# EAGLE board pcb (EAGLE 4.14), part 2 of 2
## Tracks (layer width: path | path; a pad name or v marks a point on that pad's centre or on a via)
N$27
  Top 2: 20,-1 -1,-1 -1,20
N$34
  Top 2: 140,-1 161,-1 161,20
N$35
  Top 2: 20,101 -1,101 -1,80
N$36
  Top 2: 161,80 161,101 140,101
N$37
  Bottom 2: 20,-1 -1,-1 -1,20
N$41
  Bottom 2: 140,-1 161,-1 161,20
N$42
  Bottom 2: 20,101 -1,101 -1,80
N$43
  Bottom 2: 161,80 161,101 140,101
N$172
  Top 0.15: 93.5,4 93.5,8.3
N$173
  Top 0.15: 90,7.4 91.1,6.3 91.1,3.6
N$174
  Top 0.15: 85.6,8.1 85.7,8.1 85.7,3.8
N$175
  Top 0.15: 83.4,8.1 83.2,8.1 83.2,4.1
N$176
  Top 0.15: 77.8,8.4 77.9,8.4 77.9,4.3
N$177
  Top 0.15: 75.3,4.3 75.4,4.3 75.4,8.3
N$178
  Top 0.15: 70,4 70,8.3
N$179
  Top 0.15: 67.4,4.2 67.4,7.8 67.9,8.3
N$180
  Top 0.15: 62.2,3.8 62.2,8
N$181
  Top 0.15: 59.4,4.1 59.4,7.8 59.9,8.3
N$182
  Top 0.15: 53.7,4 53.7,6.2 55.4,7.9
N$183
  Top 0.15: 52.9,8 52.9,5.9 51.2,4.2
N$184
  Bottom 0.305: 80.7,4.1 80.6,4
  Bottom 0.61: 49,4.3 49,5.2 49.6,5.8 72.8,5.8 | 72.8,5.8 80.7,5.8 | 80.7,5.8 86.4,5.8 | 86.4,5.8 88.5,5.8 88.5,3.9 | 80.7,5.8 80.7,4.1 | 72.8,5.8 72.8,4 | 91.5,30.9 91.5,27.3 90.2,26 90.2,9.6 86.4,5.8
N$185
  Top 0.15: 52.9,41.8 52.9,24.6 52.7,24.4 52.7,9.2
N$186
  Bottom 0.61: 64.9,4.1 64.9,5.7
N$187
  Bottom 0.61: 56.9,4.1 56.9,5.7
N$188
  Top 0.305: 104.6,0.6 104.7,0.6
  Top 0.406: 105,1.5 105,0.9 104.7,0.6 | 99.1,1.5 100,0.6 104.6,0.6 112.2,0.6 113.3,1.7
N$189
  Top 0.15: 101.6,20.1 101.6,23.3
N$190
  Top 0.15: 97.6,19.9 97.6,21.5 99.2,23.1
N$191
  Top 0.15: 90.8,19.1 93.3,19.1 96.6,22.4 96.6,23.6
N$192
  Top 0.15: 87.9,19.2 87.9,20 91.3,23.4
N$193
  Top 0.15: 94,23.2 94,21.4 93,20.4 89.4,20.4 89.2,20.2 89.2,16.9 90.7,15.4
N$194
  Top 0.813: 96,14.7 105.4,14.7
N$195
  Top 0.15: 104.1,23.4 104.1,20.4 105.7,18.8
N$196
  Top 0.406: 51,87 51.5,87
  Top 0.61: 46.9,91.1 51,87
N$197
  Top 0.61: 51.8,86.8 56.3,86.8
N$198
  Top 0.15: 53.6,86.7 53.7,86.7
  Top 0.406: 51.8,86.7 53.6,86.7 56.3,86.7
N$199
  Top 0.61: 56.5,79.7 56.5,85.2
N$200
  Top 0.15: 56.6,79.6 56.6,85
N$201
  Top 0.15: 52.3,73.9 55.4,73.9 55.5,73.9 55.6,74 56.5,74.9 | 56.4,74.9 56.4,74.8
  Top 0.406: 56.5,74.9 56.5,77.7 | 56.4,74.8 55.6,74
  Top 0.61: 56.4,77.7 56.4,74.9 55.4,73.9
N$202
  Top 0.15: 52.2,73.8 55.5,73.8
N$203
  Top 0.15: 59.8,66 59.8,63.2 56.7,63.2 54.5,61 54.5,57.5
N$204
  Top 0.15: 56.1,71.4 58.5,71.4 59.9,70 59.9,67.4
N$205
  Top 0.15: 53.7,57.5 53.7,60.3 50.8,63.2 45.8,63.2 45.5,63.5 45.5,66
N$206
  Top 0.15: 51.4,71.4 46.9,71.4 45.6,70.1 45.6,67.3
N$207
  Top 0.15: 83.2,77.8 84.4,77.8 84.7,77.5 84.7,75 85,74.7 85.9,74.7 86,74.8
N$208
  Bottom 0.15: 97.2,72.9 98.2,73.9 101.8,73.9 102.9,75 102.9,76.4 100.6,78.7 93.8,78.7 93.8,81.7 93.6,82.1
N$210
  Top 0.406: 89.8,87.5 89.8,91
  Top 0.61: 83.3,83 89,83 | 89,83 90.3,81.7 | 89,83 89.8,83.8 89.8,87.5 95.3,87.5 97.2,89.4 97.2,91.1 99.6,93.5 99.6,95.9
N$211
  Top 0.15: 104,78 104,64.6 105.7,62.9 118.7,62.9 120.7,60.9 120.7,52.5 118.1,49.9 118.1,46.7 118.9,45.9 123.1,45.9 123.6,45.4 125.3,45.4
N$212
  Top 0.61: 75.6,63.4 75.6,61.8
N$214
  Top 0.15: 75.1,80.8 76.3,80.8 79.5,84 79.5,87.5 81.5,89.5 85.3,89.5 86.9,91.1 87.1,91.1
N$215
  Top 0.15: 67.5,69.2 69.3,69.2 70,69.9 70,82 71.1,83.1 73.9,83.1
N$216
  Top 0.15: 73.8,80.5 71,80.5 70.5,80 70.5,67.2 69.8,66.5 68.1,66.5
N$217
  Top 0.61: 74.9,69 74.9,72.3 77.3,74.7 77.3,77.9 | 81.6,83 81,83 80.3,82.3 80.3,77.9 | 80.3,77.9 80.3,76.4 81.3,75.4 | 77.3,77.9 75.8,77.9 | 77.3,77.9 80.3,77.9
N$218
  Top 0.15: 75.9,68.7 75.8,68.7
  Top 0.61: 75.9,68.7 76.9,67.7 76.9,65.3 75.9,64.3
N$219
  Bottom 0.61: 68.4,63.9 73.9,63.9
N$220
  Top 0.8: 37.1,45.7 35.9,45.7
  Top 0.813: 37.1,45.7 37.7,45.1 37.6,43.3 40.7,40.2 40.7,37 42.5,35.2 42.5,18.6 43.3,17.8
N$221
  Top 0.15: 55.3,57.4 55.3,61.1 56.3,62.1 64.7,62.1 66.2,63.6
N$222
  Top 0.15: 52.9,57.3 52.9,60.2 50.5,62.6 45.7,62.6 44.7,63.6 44.7,70.2 46.7,72.2 50.4,72.2 50.4,76.3 51.4,77.3
N$223
  Top 0.15: 52.1,57.6 52.1,60.1 50.2,62 45.5,62 44.2,63.3 44.2,70.5 46.4,72.7 49.9,72.7 49.9,76.3 48.9,77.3
N$224
  Bottom 0.813: 21.2,73.5 26.7,73.5 30.2,77 39.8,77 48.9,86.1
N$225
  Top 0.15: 48.9,57.3 48.9,60.9 48.4,61.4 45.3,61.4 43.7,63 43.7,91.3
N$226
  Top 0.15: 48.1,57.5 48.1,60.9 45.1,60.9 43.2,62.8 43.2,89.2 41.5,90.9
N$227
  Top 0.15: 47.3,57.5 47.3,60.4 44.9,60.4 42.7,62.6 42.7,87.9 39.4,91.2
N$228
  Bottom 0.813: 48.9,86.7 48.9,88.7 49.6,89.4 57.5,89.4 61.5,93.4
N$229
  Top 0.61: 56.2,73.8 61.9,73.8
N$230
  Top 0.61: 62.5,73.1 62.5,68.1 66.4,64.2
N$231
  Top 0.15: 106,71 109.1,71 110.8,72.7
N$232
  Top 0.15: 106,71.7 108.6,71.7 109.5,72.6 109.5,74.1 109.8,74.4 114.5,74.4 115.2,75.1
N$233
  Top 0.15: 99.3,57.8 99.3,60.8 | 99.3,60.8 99.3,62.6 | 99.3,60.8 117.8,60.8 119.1,59.5 119.1,51.5 117.5,49.9 117.5,46.6 119.2,44.9 122.4,44.9 123.6,43.7 135.7,43.7 136.1,44.1
N$234
  Top 0.15: 99.3,55.6 96.5,55.6 95.3,56.8
N$235
  Top 0.15: 98.4,62.6 98.4,59.7 97.6,58.9 93.9,58.9 93,58
N$236
  Top 0.15: 94.9,56 94.9,57 | 94.9,56 94.9,54.5 | 94.9,56 92,56 91.6,56.4 91.6,58.7 92.3,59.4 95.1,59.4 95.3,59.6 95.3,62.5
N$237
  Top 0.15: 98.1,83.7 98.1,84.5 98.4,84.8 101.9,84.8 102.5,85.4 102.5,86.1
N$238
  Top 0.406: 49.2,22.9 49.2,23.1 43.9,17.8
N$239
  Top 0.406: 11.1,56.1 11.4,56.1
  Top 0.813: 11,56.2 11.1,56.1
  Top 1.422: 5.5,56.2 11,56.2 | 11.1,56.1 12.4,54.8
N$240
  Top 1.016: 14.4,54.6 23.9,54.6 24.7,55.4
N$241
  Top 0.406: 24.4,45.7 35.4,45.7
N$242
  Top 0.813: 39.6,53.1 39.6,49.6 35.6,45.6
N$243
  Bottom 0.61: 15.3,23.1 18.3,23.1 18.7,23.5
N$245
  Top 0.15: 59.3,41.5 62.1,41.5 62.6,41 65.8,41 65.8,40.2
N$246
  Top 0.2: 58.5,41.5 58.5,41 58.8,40.7 61.9,40.7 62.5,40.1
N$247
  Top 0.15: 66.3,39.5 68.8,39.5
N$248
  Top 0.15: 69.2,33.5 69.2,36.2
N$249
  Top 0.15: 69.8,33.1 71.1,33.1 72,32.2
N$250
  Top 0.15: 65.8,31.6 69.1,31.6
N$251
  Top 0.15: 65.7,33.8 65.6,33.7
  Top 0.2: 63,39 63,38.3 63.6,37.7 65.7,37.7 65.7,33.8
N$253
  Top 0.15: 57.7,41.7 57.7,40.7 58.3,40.1 61.7,40.1 61.7,38.3 62.2,37.8 62.8,37.8 63.5,37.1 65.1,37.1 65.1,35.1 64.5,35.1 64.1,34.7 64.1,31.8 64.4,31.5 65.1,31.5
N$254
  Top 0.15: 61.2,44.4 62.1,44.4 62.1,42.2 62.9,41.4 66.3,41.4 66.3,40.9 71.1,40.9 72.1,39.9
N$255
  Top 0.15: 74,37.4 74,37.7 75.2,38.9 75.2,40 74.3,40.9 71.8,40.9 71.4,41.3 66.8,41.3 66.8,41.9 63.1,41.9 62.6,42.4 62.6,45.2 61.5,45.2
N$256
  Top 0.2: 73.9,28.9 77.6,28.9
N$257
  Top 0.15: 35.8,41.4 37.5,41.4 38.6,40.3 38.6,39.3
N$258
  Top 0.15: 31.8,37.8 31.8,41.3
N$259
  Top 0.15: 25,38.1 25,39.6 25.7,40.3 27.2,40.3 28.1,41.2
N$260
  Top 0.15: 25.6,27.8 25.5,27.9 25.5,28.8 23.8,30.5 23.8,41.3
N$261
  Top 0.15: 36.9,34.2 36.9,37 36.2,37.7 34.4,37.7 34.3,37.6
N$262
  Bottom 0.61: 15.3,26.3 18.6,26.3 18.7,26.2
N$263
  Top 0.15: 27.2,37.5 29.9,37.5 31.1,36.3 33.1,36.3 33.1,34.3
N$264
  Top 0.15: 33.1,26.7 33.1,26.2 32.5,25.6 29.1,25.6 27.8,26.9
N$265
  Top 0.15: 34.3,31.6 34.3,32.8 | 31.8,28.3 31.8,31.6 | 31.8,31.6 31.8,32.8 | 31.8,31.6 34.3,31.6 | 38.1,31.6 38.1,28.3 38.2,28.2 | 38.1,31.6 38.1,33 | 34.3,31.6 38.1,31.6
N$266
  Top 0.15: 34.3,27.5 35.5,27.5 35.6,27.4
N$267
  Top 0.15: 35.6,26.7 35.6,25.2 37.5,23.3 37.5,17.7 | 37.5,17.7 36.3,17.7 | 37.5,17.7 43.2,17.7
N$269
  Top 0.15: 100.9,78.4 100.9,81.7 99.8,82.8
N$270
  Top 0.15: 101.7,78.3 101.7,82.4 104.3,85 104.3,86.4
N$271
  Top 0.15: 102.4,78.3 102.4,82.3 105.5,85.4 109.7,85.4
N$272
  Top 0.15: 53.5,96.2 61.2,96.2
N$273
  Top 0.15: 61.8,96.2 64,96.2
N$274
  Top 0.2: 66.9,81.6 66.9,84.5
N$275
  Top 0.15: 130.5,66.2 130.5,68.6 130.4,68.7
N$276
  Top 0.15: 120,49.8 123.2,49.8 124.3,50.9
N$277
  Top 0.61: 143.8,36.7 143.8,41.1
N$278
  Top 0.15: 144.2,74.5 148.2,74.5
N$279
  Top 0.15: 144.2,72 148.5,72
N$280
  Top 0.15: 144.2,69.4 148.3,69.4
N$281
  Top 0.15: 144.1,66.9 148.3,66.9
N$282
  Top 0.15: 144.3,64.4 148.3,64.4
N$283
  Top 0.15: 144.3,61.8 148.3,61.8
N$284
  Top 0.61: 151.3,61.8 151.3,74.2
N$285
  Top 0.305: 141.9,61.8 141.9,74.5
N$286
  Top 0.305: 137.5,61.1 140.1,61.1 140.7,61.7 141.9,61.7
N$287
  Top 0.406: 137.6,74.3 138.4,74.3 138.9,73.8 138.9,64.9 137.5,63.5
N$288
  Top 0.305: 123.6,58.7 126.3,58.7 127.7,57.3 133.9,57.3 133.9,62.2 135.1,63.4
N$289
  Top 0.15: 137.7,58.9 138.6,58.9 139.1,58.4 139.1,52.7 139.2,52.6
N$290
  Top 0.15: 14.4,52.1 32.2,52.1 35.6,55.6 45.3,55.6
N$291
  Top 0.15: 45.7,54.8 35.6,54.8 32.3,51.5 16.3,51.5 14.6,49.8
N$292
  Bottom 0.61: 16,40.4 18.7,40.4
N$293
  Bottom 0.61: 16,37.4 18.8,37.4
N$294
  Bottom 0.813: 14.7,42.9 18.9,42.9
N$295
  Bottom 0.61: 20.5,23.8 24.4,23.8 25.6,22.6
N$296
  Top 0.813: 30.1,14.9 30.1,13.2 30.8,12.5 32.2,12.5 33.1,11.6 33.1,7.8 34.2,6.7 34.2,3.7 34.8,3.1 36.1,3.1
N$297
  Bottom 0.8: 20.6,31.8 14.5,31.8 13.3,33 13.3,41.4 14.1,42.2
  Bottom 0.813: 20.8,28.7 20.4,28.6 | 20.8,28.7 20.8,31.8 20.6,31.8 | 20.8,28.7 21.8,28.7 21.8,28
N$298
  Bottom 0.406: 26.8,6.8 26.7,6.9 24.4,6.9 24.4,9.1 24.5,9.2
  Bottom 0.813: 41.2,9.1 41.2,6.3 39.8,4.9 34.8,4.9 31.7,1.9 26.8,6.8 24.4,6.8 24.4,9.4
N$299
  Bottom 0.61: 20.8,26.2 32.3,26.2 36.1,22.4
N$300  (via drill 0.7)  (1 unrouted)
  Bottom 0.406: 10.8,47 16,47 17.4,45.6
  Bottom 0.61: 13,54.5 11.7,54.5 10.8,53.6 10.8,47 10.8,44.2 11.5,43.5
  other vias: 17.4,45.5
N$301
  Bottom 0.61: 11.6,42.5 11.6,30.2 12.5,29.3
N$302
  Bottom 0.813: 21.8,27.9 32.9,27.9 38.5,22.4 38.5,20.8 34.8,17.1 34.8,11.7 35.8,10.7
N$303
  Top 0.305: 9.5,16.2 9.5,21.6 10.6,22.7
N$304
  Top 0.305: 4.9,13.5 6.9,13.5 | 6.9,13.5 9.4,16 | 15.7,10.7 9.7,10.7 6.9,13.5
N$305
  Top 0.305: 15.8,10.3 15.8,8.8 19.2,5.4
N$306
  Top 0.305: 17.3,2.7 18.5,2.7 | 18.5,2.7 18.7,2.7 19.6,3.6 19.6,5 | 18.5,2.7 28.2,2.7 28.3,2.8
N$307
  Top 0.305: 28.4,2.7 28.7,2.7 30.7,4.7
N$308
  Top 0.61: 19.4,10.8 19.4,9.7 24.1,5.1 25.5,5.1
N$309
  Bottom 0.305: 2.7,13.5 2.7,11.9 3.5,11.1 9.3,11.1 12.3,8.1 12.3,2.5 14.2,0.6 21.4,0.6 25.8,5
N$310
  Top 0.15: 32.4,14.9 35.3,14.9 35.8,14.4
N$311
  Top 0.15: 33,17.7 33,17 33.5,16.5 33.5,16 35.1,16 | 35.1,16 35.2,16 | 35.1,16 39.6,16 41.2,14.4
N$312  (via drill 0.7)
  Top 0.406: v1.4,54 1.4,49.9 2,49.3 5.5,49.3
  Bottom 0.406: 5.8,74.2 5.8,61.6 8,59.4 8,55.6 6.3,54 v1.4,54 | 5.8,74.2 5.8,74.3 | 5.8,74.2 5.8,74.7 6.2,75.1 9.6,75.1
N$313
  Top 0.15: 82.1,92.8 82.1,93.9 81.4,94.6 78.9,94.6 78.1,95.4 78.1,98.4 78.8,99.1 95.1,99.1 95.1,98.1
N$314
  Bottom 0.813: 103.1,96 103.1,94.8 103.6,94.3 103.6,89.6 104.9,88.3 118.8,88.3 119.2,87.9 127.1,87.9 128.2,89 128.2,91.7 126,93.9 126,96.2
N$315
  Top 0.61: 156.5,40.7 156.5,48.6
N$316
  Top 0.305: 157.8,29.1 157.8,28.5
  Top 0.61: 157.8,29.1 159.4,30.7 159.4,38.2 156.8,40.8
N$317
  Top 0.61: 150.4,31.4 156.7,31.4
N$318
  Top 0.61: 144.1,41.1 153.8,41.1
N$319
  Top 0.61: 153.9,41.2 153.9,43.5 154,43.6
N$320
  Top 0.61: 155.2,54.3 156.4,55.5
N$321
  Top 0.3: 154.1,83.4 154.1,83.6
  Top 0.61: 151.3,74.5 151.3,76 154.1,78.8 154.1,83.4 | 154.1,83.6 156.8,83.6 158,84.8 158,85.7 155.8,87.9 153.7,87.9
N$322
  Top 0.15: 143.7,86.5 143.7,85.7 144.3,85.1 148.6,85.1 150.1,83.6 151.8,83.6 153.4,85.2 155.2,85.2
N$323
  Bottom 0.15: 156.4,88.2 153.8,88.2 153.6,88
N$324
  Bottom 0.15: 136,74.8 136.1,74.8
  Bottom 0.406: 146.1,86.4 146.1,85.2 147.4,83.9 | 147.4,83.9 148.3,83 | 147.4,83.9 136.1,83.9 136.1,74.8
N$325
  Bottom 0.15: 155.8,81.9 154.6,81.9 153.5,80.8 143.9,80.8 142.8,79.7
N$326
  Bottom 0.15: 137.5,80.7 141.9,80.7 142.7,79.9
N$327
  Bottom 0.15: 131.3,63.9 131.5,63.9 134.9,67.3 139.1,67.3 139.5,67.7 145.7,67.7 147.8,65.6 155,65.6 156.5,67.1
N$328
  Bottom 0.15: 158.2,67.5 159.1,68.4 159.1,74.4 | 159.1,74.4 159.1,87.6 158.8,87.6 158.6,87.8 | 159.1,74.4 158.3,73.6
N$329
  Top 0.813: 147.7,23.7 149.3,22.1 156.7,22.1 156.7,23.1
N$330
  Top 0.61: 156.5,25.8 155.3,25.8 154.6,26.5 154.6,31.3
N$331
  Top 0.305: 158,28.8 157.7,28.8
  Top 0.5: 158,28.8 159.3,27.5 159.3,24.3 158.7,23.7 | 158.7,23.7 158.6,23.6 | 158.7,23.7 158.5,23.5 157.9,23.5 157.7,23.3
N$332
  Top 0.305: 157.1,17.5 157.1,15.2 156.9,15
N$333
  Top 0.305: 124.4,52.8 124.4,56.5 122.5,58.4
N$334
  Top 0.15: 117.2,55.4 117.2,52.4 116.6,51.8 112.6,51.8
N$335
  Top 0.15: 102.8,55.4 102.8,52.2 103.2,51.8 108,51.8
N$336
  Top 0.15: 108.7,49.5 111.7,49.5
N$337
  Top 0.61: 15,88.9 15,96.1
N$338
  Top 0.15: 38.7,13.3 38.7,12.6 46.5,12.6
N$339
  Top 0.15: 44.2,13.3 45.2,13.3 45.9,14 50.3,14 50.3,11 49.8,10.5 48.9,10.5 48.9,9
N$340
  Top 0.813: 43.9,9.9 45.9,9.9 46.8,9
N$341
  Top 0.406: 77.9,2 77.9,1.2
N$342
  Top 0.15: 53.7,41.7 53.7,26.2 54.4,25.5 55.5,25.5 56.3,24.7 56.3,12.1 59.9,8.5
N$343
  Top 0.15: 54.5,41.7 54.5,26.7 55,26.2 55.7,26.2 56.8,25.1 56.8,12.6 59.8,9.6 66,9.6 67,8.6
N$344
  Top 0.15: 55.3,41.7 55.3,26.9 55.9,26.9 57.3,25.5 57.3,12.9 60.2,10 73.7,10 75.3,8.4
N$345
  Top 0.15: 56.1,41.7 56.1,27.6 57.9,25.8 57.9,13.1 60.5,10.5 81.3,10.5 83.1,8.7
N$346
  Top 0.15: 56.9,41.7 56.9,27.5 58.4,26 58.4,13.4 60.9,10.9 88.2,10.9 90.5,8.6
N$347
  Top 0.15: 105.7,69.3 109.3,69.3 111.2,71.2 115.6,71.2 116.5,72.1 116.5,73.2 121.6,73.2 122,73.6
N$348
  Top 0.15: 106,68.5 109.3,68.5 111.5,70.7 115.7,70.7 117.1,72.1 117.1,72.6 124.9,72.6 126.1,71.4 129.4,71.4
N$349
  Top 0.15: 105.9,67.7 118.4,67.7 122.2,63.9
N$350
  Top 0.15: 106,66.9 117.4,66.9 121.8,62.5 128.6,62.5 129.7,61.4
N$351
  Top 0.15: 122.2,68.9 122.2,71.2
N$352
  Top 0.15: 124,66.3 124.8,66.3 127.4,63.7 129.7,63.7
N$354
  Top 0.15: 128.5,84.7 125.4,84.7 | 128.5,84.7 129.1,84.1 129.1,82.3 | 143.5,87.5 131.3,87.5 128.5,84.7
N$355
  Top 0.15: 122.4,84.8 121.4,85.8 117.6,85.8
N$356
  Top 0.305: 135.5,72 134.2,73.3 134.2,75.2 135.1,76.1 150,76.1 150,59.2 150.9,58.3 156.7,58.3
N$357
  Top 0.61: 151.3,61.7 151.3,60.6 151.9,60 158.6,60 159.4,59.2 159.4,56.9 158.5,56
N$358
  Top 0.15: 106,70.1 109.2,70.1 110.7,71.6 115.3,71.6 116,72.3 116,73.6 120.6,73.6 120.9,73.9 120.9,74.6 121.4,75.1 127.1,75.1 127.7,74.5 127.7,72.9 128.2,72.4 132.2,72.4 132.5,72.1 132.5,60.6 131.9,60 122,60 121.2,59.2 121.2,58.1 121.7,57.6 122.4,57.6 123.7,56.3 123.7,53.7 122.9,52.9 122.9,50.8 119.7,50.8 118.7,49.8 118.7,47.1 119.2,46.6 120.6,46.6 121.4,47.4 121.4,49.2 130.6,49.2 131.2,49.8 131.2,51.9 131.5,52.2 137.1,52.2
N$359
  Bottom 0.15: 156.6,69.7 155.1,68.2 139,68.2 138.6,67.8 132.9,67.8 131.8,68.9
N$360
  Bottom 0.15: 156.4,76 155.5,76 155.1,75.6 155.1,71.8 154,70.7 139,70.7 139,69.2 138.2,68.4 134,68.4 132.2,70.2 129.3,70.2 128.5,71 123.6,71
N$361
  Bottom 0.15: 152.2,82.9 152.2,84 153.4,85.2 151.1,87.5 151.1,88 152.5,89.4 155.1,89.4 155.6,89.9 159.2,89.9 159.6,89.5 159.6,61.5 | 159.6,61.5 159.6,42.1 157.3,39.8 155.1,39.8 154.1,38.8 | 159.6,61.5 158.2,61.5
N$363
  Top 0.406: 99.7,95.6 99.7,96.8
  Top 0.61: 104.9,90.4 99.7,95.6
N$364  (via drill 0.5)
  Top 0.15: 90,75.8 89.2,75.8 87.9,74.5 87.9,72.2 v86.2,70.5
  Bottom 0.15: 102,50.3 102,52.9 100.1,54.8 88.4,54.8 88.1,54.5 87,54.5 86.6,54.9 86.6,70.1 v86.2,70.5
N$365
  Bottom 0.15: 78.7,89.7 78.7,89.8
  Bottom 0.2: 78.7,78.9 78.7,84.8
  Bottom 0.813: 78.7,89.8 79.7,90.8 | 78.7,84.8 78.7,89.7
N$366
  Top 0.15: 50.5,57.1 50.5,56.2 47,56.2 45.5,57.7 33.7,57.7 29.6,61.8 12.1,61.8 9.8,59.5 1,59.5 0.4,60.1 0.4,78.9 1.4,79.9
N$367
  Top 0.15: 17.5,96.2 17.5,91.1 16.2,89.8 16.2,85.1 11.3,80.2
N$368
  Top 0.406: 70,1.3 70,2.1
N$369
  Top 0.15: 10.9,62.4 29.8,62.4 34,58.2 45.5,58.2 46,58.7
N$370
  Top 0.15: 3.2,62.4 7.7,62.4 8.7,63.4 11.6,63.4 12.1,62.9 30,62.9 34.2,58.7 43.5,58.7 44.4,59.6
N$371
  Top 0.15: 10.5,67.4 12.1,67.4 13.8,69.1 13.8,82.1 16.9,85.2 16.9,86.4 18.6,88.1 18.6,92.7 19.1,93.2 25,93.2 25.9,94.1 25.9,96
N$372  (via drill 0.5)
  Bottom 0.15: 44.4,59.7 45.3,59.7 45.6,60 47,60 47.5,59.5 47.5,56.6 48.5,55.6 48.5,53.8 v48.3,53.6
N$373  (via drill 0.5)
  Top 0.15: v57.3,60.5 57.4,60.6
  Top 0.2: 56.9,57.3 56.9,60.1 v57.3,60.5
  Bottom 0.15: 67,73.1 67.1,73.2 | 68.2,54.4 68.2,54.3
  Bottom 0.2: v57.3,60.5 61.9,60.5 | 61.9,60.5 63.4,60.5 65.5,62.6 65.5,64.7 66,65.2 69.3,65.2 70.1,66 70.1,69.7 68.9,70.9 67.5,70.9 67,71.4 67,73.1 | 61.9,60.5 61.9,54.9 62.4,54.4 68.2,54.4
N$374
  Top 0.15: 57.7,57 57.7,56.1 51.9,56.1 51.9,55.2 47.9,55.2 47.4,54.6
N$375
  Top 0.15: 58.5,57 58.5,55.6 52.5,55.6 52.5,54.7 49.4,54.7 48.1,53.4
N$376
  Top 0.15: 3.4,77.7 4.4,77.7 4.9,78.2 4.9,85.7 11.1,91.9 11.1,99.7 35.3,99.7 36.7,98.3
N$377
  Top 0.15: 59.3,57.1 59.3,55.1 53.2,55.1 53.2,54.2 50.8,54.2 50,53.4
N$378
  Top 0.15: 3.7,70.1 4.1,70.1 5.4,71.4 5.4,85.5 11.6,91.7 11.6,93.6 13.5,95.7 13.5,99.3 33.9,99.3 34.6,98.4
N$379  (via drill 0.5)
  Top 0.15: 9.3,69.8 8.4,69.8 8.1,69.5 8.1,64.7 8.9,63.9 11.8,63.9 12.4,63.3 30.3,63.3 34.4,59.2 42.1,59.2 v43.3,60.4
  Bottom 0.15: 49.8,53.4 49,54.2 49,55.7 48,56.7 48,59.9 47.4,60.5 43.4,60.5 v43.3,60.4
N$380
  Bottom 0.15: 1.4,62.4 0.7,62.4 0.4,62.7 0.4,84.3 1.5,85.4
N$381
  Bottom 0.15: 8.1,72.6 8.1,63.4 9.1,62.4 | 8.1,72.6 8.1,72.7 | 8.1,72.6 8.1,73.4 8.5,73.8 12,73.8 12.6,74.4 12.6,75.9 12.1,76.4 8.3,76.4 7.8,76.9 7.8,83.4 9.3,84.9
N$382
  Top 0.15: 1.6,74.6 1.6,72.8 1.7,72.7
N$383
  Bottom 0.15: 1.6,72.3 1.5,72.3 0.9,71.7 0.9,64.1 1.3,63.7 3.8,63.7 4.3,63.2 4.3,56.8
N$384
  Top 0.15: 11,82.7 11.9,82.7 12.5,83.3 12.5,94 13.9,95.4 13.9,98.9 26.8,98.9 27.3,98.4 27.3,95.9 28.4,94.8 37,94.8 38.3,96.1 38.3,98.7 38.8,99.2 43.8,99.2 44.6,98.4
N$385
  Top 0.15: 10.9,65 10.9,65.4 14.5,69 14.5,82.1 17.5,85.2 17.5,86.3 19.2,88 19.2,90.9 20.4,92.1 34.9,92.1 38,95.2 41.2,95.2 42,96
N$386
  Top 0.15: 4.5,68.7 4.5,66.1 3.6,65.2
N$387
  Top 0.15: 69.7,14.6 69.7,18.6 72,20.9
N$388
  Top 0.15: 68.4,21.8 67.1,21.8 | 68.4,21.8 69.6,21.8 | 68.4,21.8 68.4,11.7 89.5,11.7 91,10.2 94.5,10.2 96,8.7 96,6 96.4,5.6 125.4,5.6 127.2,3.8
N$389
  Top 0.15: 64.6,14.2 67.2,14.2
N$390
  Top 0.15: 67.1,13.1 67.1,11.3 89.2,11.3 90.8,9.7 94.3,9.7 95.4,8.6 95.4,5.8 96.1,5.1 120,5.1 121.3,3.8
N$391
  Bottom 0.813: 95.9,10.7 93.7,8.8 93.7,4
N$392
  Top 1.016: 5.7,49.3 5.7,50.7
N$393
  Top 0.15: 69.6,13.1 69.6,12.2 81.8,12.2 82.3,12.7 82.3,15.8
N$395
  Bottom 0.15: 91.5,32.7 91.5,36.3
N$396
  Bottom 0.61: 150.2,19.7 151.4,19.7 154.8,16.3 159.1,16.3 159.1,4.5 156,1.4 150.9,1.4 144.4,7.9 119.8,7.9 115.5,12.2
N$397
  Top 0.15: 127.8,45.3 132.7,45.3
N$398
  Bottom 0.15: 104.1,43.3 115,43.3 115.3,43
N$399
  Top 0.15: 122.8,15.2 122.8,17
N$400
  Top 0.15: 124.2,14.4 124.2,13.5 125.4,12.3 125.4,11.4 133,3.8
N$401
  Top 0.15: 116.2,17.7 116.2,19.5
N$402
  Top 0.15: 107.8,14.3 107.7,14.2
  Top 0.813: 122.1,27.4 119.2,27.4 117.3,29.3 113.5,29.3 112,27.8 112,23.9 109.7,21.6 109.7,15 109,14.3 107.8,14.3
N$403
  Top 0.15: 116.5,22.3 120.1,22.3 122.3,20.1
N$404
  Top 0.15: 122.1,19.6 122.1,18.6 121.4,17.9 121.4,7.6 122.9,6.1 126.9,6.1 128.8,4.2 128.8,1.9 | 128.8,1.9 128.8,1.3 128.1,0.6 126.9,0.6 125.6,1.9 | 128.8,1.9 130.7,1.9
N$405
  Top 0.15: 114.7,20 114.7,20.4 113.6,21.5 113.6,23 114,23.4 119.8,23.4 122.1,21.1 124.3,21.1 125.2,20.2 125.2,13.2 125.9,12.5 125.9,11.6 131.1,6.4 136.7,6.4 139.4,3.7
N$406
  Top 0.15: 131.3,1.7 131.3,1.4 131.9,0.8 135.9,0.8 | 135.9,0.8 136,0.8 136.8,1.6 | 135.9,0.8 145.1,0.8 147.4,3.1
N$407
  Top 0.15: 119.1,1.6 119.1,0.9 119.4,0.6 123.7,0.6 124.7,1.6
N$408
  Bottom 0.15: 106.7,23.7 106.7,11.6 111.1,7.3 111.1,2.9 110.6,3.3
N$409
  Bottom 0.15: 109.3,23.4 109.3,22.4 108.7,21.8 107.2,21.8 107.2,12 115.5,3.7
N$410
  Bottom 0.15: 99.3,30.9 101.1,29.1 105.1,29.1 105.7,28.5 105.7,5.6 107.6,3.7
N$411
  Bottom 0.15: 96.6,30.8 97.3,30.8 99.5,28.6 104.8,28.6 105.2,28.2 105.2,5.6 102.6,3
N$412
  Top 0.15: 84.1,16.3 84.1,18.2 87.1,21.1 87.5,21.5 88.6,21.5 90.2,23.1 90.2,26 91.4,27.2 91.4,31
N$413
  Top 0.61: 27.5,14 27.1,14
  Top 0.813: 30.2,15.3 28.8,15.3 27.5,14
N$414
  Bottom 0.406: 38.7,10.8 38.7,19.1 40.1,20.5 40.1,23.3 34.4,29 23.4,29 22.5,29.9 22.5,40.7 22.9,41.1 22.9,48 21.7,49.2
N$415
  Top 0.61: 15.1,33.7 13.7,32.3 13.7,18.9 16.1,16.5 17.3,16.5
N$416
  Top 0.61: 19.4,10.7 19.4,17.6 18.7,18.3 16.2,18.3 15.4,19.1 15.4,22.9 16.3,23.8 18.7,23.8
N$417
  Top 0.406: 31.2,8.9 31.2,7.9 32.8,6.3 32.8,2.5 34.8,0.5 37.6,0.5 38.4,1.3
N$418
  Bottom 0.61: 13.2,16.2 13.2,14 14.5,12.7 19.8,12.7 21.6,10.9
N$419
  Top 0.61: 24.2,16.6 24.3,16.6 23.6,16.6
  Top 0.813: 24.3,16.6 27.4,16.6 | 24.2,16.6 22.6,18.2 22.6,38.7 21,40.3 | 23.6,16.6 21.7,14.7 21.7,10.4 21.6,10.3
N$420
  Top 0.15: 48.3,11.7 48.3,10.9 45.6,10.9 44.6,11.9 39.6,11.9 38.5,10.8
N$421
  Top 0.813: 32,73.1 32,67.3 29.8,65.1 16.8,65.1
N$422
  Top 0.406: 85.7,1.2 85.7,2.3
N$423
  Bottom 0.406: 41.3,3.2 41,3.2
N$424
  Top 0.15: 36.9,26.8 36.9,25.6 38,24.5 40.8,24.5 41.7,25.4 41.7,34.7 39.4,37
N$425
  Top 0.406: 23.9,45.7 17.6,45.7 10.6,38.6 10.6,22.8
N$426  (via drill 0.5)
  Bottom 0.15: v40.9,49.1 39.9,49.1 39.5,48.7 39.5,46.1 29.7,36.3 29.7,36.1
N$427
  Top 0.15: 30.5,34.2 30.5,35.2 29.7,36
N$428
  Top 0.15: 30.5,28.3 30.5,29.2 29.6,30.1 28.5,30.1 28.2,30.4 28.2,34.8
N$429  (via drill 0.5)
  Bottom 0.15: 40.7,47.6 40.7,46.6 30.9,36.8 30.9,35.3 30.5,34.9 v28.2,34.9
N$430
  Top 0.15: 45.5,50.8 43.6,50.8 43.2,50.4 43.2,49.7 41.2,47.7
N$431
  Bottom 0.813: 54.6,22.8 54.6,18.6 46.7,10.5
N$432
  Bottom 0.61: 36.1,22.2 36.1,20.4 33.1,17.4 33.1,15 28.8,10.7
N$433
  Bottom 0.813: 79.5,92.1 76.1,92.1 74.9,93.3 74.9,97.5 74.1,98.3 59.6,98.3 58.9,97.6 58.9,94.5 59.8,93.6 61.6,93.6
N$434
  Top 0.15: 30.6,18.4 28.6,18.4 28,19
N$435
  Bottom 0.15: 28,18.9 30.1,16.8 30.1,14.5 27,11.4 27,8.5 28.5,7 38.4,7 39.9,8.5 39.9,11.3 40.5,11.9 41.4,11.9
  Bottom 0.406: 28,18.9 27.9,18.9
N$436
  Top 0.813: 5.5,50.8 8.1,50.8 12,46.9 24.6,46.9 25.6,47.9
N$437
  Bottom 0.813: 54.3,23.5 46.7,31.3 25.6,31.3 25.6,47.9
N$438
  Top 0.15: 51.3,57 51.3,55.7 47,55.7 45.4,57.3 33.4,57.3 29.4,61.3 12.4,61.3 9.7,58.6 6.8,58.6
N$439
  Top 0.813: 93.6,1.9 93.6,1.2
N$440  (via drill 0.7)
  Top 0.813: v47.1,6.5 47.1,8.2
  Bottom 0.7: 140.4,0.6 141.1,1.3
  Bottom 0.813: v47.1,6.5 46.4,5.8 46.4,1.3 47.1,0.6 140.4,0.6
N$441
  Bottom 0.813: 141.2,1.4 144,4.2 144,5.5
N$442  (via drill 0.7)
  Top 0.305: 144,3.5 v144,5.6
  Top 0.406: 144,7.2 143.9,7.3
  Top 0.813: v144,5.6 144,7.2
N$443
  Top 0.813: 50.2,1.1 49.9,1.1 | 50.2,1.1 93.6,1.1 | 50.2,1.1 47.1,1.1 46.3,1.9 46.3,3.8 48.5,6 51.2,6 51.2,7.8
N$444
  Top 0.305: 53.7,2.3 53.7,2.2
N$445
  Top 0.406: 53.7,1.1 53.7,2
N$446
  Top 0.406: 61.9,1.9 61.9,1.2
N$447
  Top 0.2: 96.6,1.6 96.6,0.3 42.5,0.3 41.3,1.5
N$448
  Bottom 0.8: 39.9,54.8 39.2,55.5 29,55.5
  Bottom 0.813: 39.9,54.8 39.9,53.5
N$449
  Top 0.15: 127.5,16.2 127.5,14.1 129.7,11.9
N$450
  Top 0.305: 98.7,3.3 97.4,4.6 95.7,4.6 95.1,3.9 95.1,1.2 93.7,1.2
N$451
  Top 0.15: 132.6,17.5 131.8,18.3 128.5,18.3 127.5,17.3
N$452
  Top 0.15: 140.2,12.9 140.2,17.2 140.3,17.3
N$453
  Top 0.305: 135.1,12.8 135.1,13.1 137.7,15.7
N$454
  Top 0.15: 140.5,24.1 140.5,22.3 135.5,17.3
N$455
  Top 0.15: 157,20.4 152.9,20.4 152.9,20.9 145.5,20.9 142.7,18.1
N$456
  Top 0.15: 135.4,15.7 135.4,14.6 133.5,12.7 133.5,10.7 134.2,10 135.5,10 136.3,10.8 136.3,13.1 136.9,13.7 138,13.7 138.8,12.9 138.8,8.8 139.8,7.8 142,7.8
N$457
  Top 0.15: 141.9,3.5 141.9,4.8 137.5,9.2 137.5,10.9 136,9.4 129.9,9.5
N$458
  Top 0.15: 142.6,24.2 142.6,20 140.7,18.1
N$459
  Bottom 0.305: 131.7,24 131.7,23.5 137.7,17.5
N$460
  Top 0.813: 129.4,26 129.4,27.3 124.1,27.3
N$461
  Bottom 0.15: 156.8,12 155.8,11 151.5,11 150.1,9.6 134.6,9.6 133,11.2 133,13.6
N$462
  Top 0.15: 156.7,17.9 151.5,17.9 150.9,18.5 148.9,18.5 148,19.4
N$463
  Top 0.15: 150.3,23.9 150.3,24 151.8,25.5 151.8,29.5 151.2,30.1 149.8,30.1 149,30.9 149,33 148.2,33.8 143.3,33.8 142.6,34.5 142.6,39.8 141.7,40.7
N$464
  Top 0.15: 147.9,17 148,17.4 146.3,15.7 146.3,6.2 146.9,5.6
N$465
  Top 0.813: 147.5,19.6 146.1,19.6 145.4,18.9 145.4,9.3 144,7.9
N$466
  Top 0.61: 150.3,31.6 150.3,34.2 149,35.5 144.1,35.5
N$467
  Top 0.813: 147.7,23.7 147.7,26.3
N$468
  Top 0.61: 157.7,22.9 157.5,22.9
  Top 0.813: 157.7,22.9 159.3,21.3 159.3,11.7 158.4,10.8 155.2,10.8 154.5,11.5 151.8,11.5 150.7,10.4 149.2,10.4 147.9,11.7
N$469
  Top 0.813: 147.6,12.2 147.6,14.5
N$470
  Top 0.15: 150.5,12.1 150.8,12.1 152.3,13.6 158,13.6 158.6,14.2 158.6,20.8 158.1,21.3 147.7,21.3 146.2,22.8 146.2,24.8 141.3,29.7 141.3,34.9
N$471
  Bottom 0.813: 147.6,31.4 147.6,32.3 153.9,38.6
N$472
  Bottom 0.813: 147.7,19.7 147.7,20.5 148.5,21.3 152.1,21.3 153.6,22.8 153.6,33.3 151.2,35.7
N$473
  Bottom 0.61: 147.8,29 150.1,31.3
N$474
  Bottom 0.305: 147.8,17.2 147.7,17.2
  Bottom 0.61: 147.8,17.2 150.3,19.7
N$475
  Bottom 0.61: 147.7,17.3 145.9,19.1 145.9,20.6 147.6,22.3 151.2,22.3 152.1,23.2 152.1,29.6 150.5,31.2
N$476
  Top 0.15: 103.2,78.5 103.2,79.8 103.5,80.1 109.9,80.1
N$477
  Top 0.406: 117.5,98.1 119.1,98.1 120.1,97.1
N$478
  Top 0.15: 99.9,83.2 101,83.2 101.4,83.6
N$479
  Top 0.15: 113.6,79.2 113.6,77.7 113.1,77.2
N$480
  Bottom 0.15: 113.1,77.1 108.2,77.1 101.6,83.7
N$481
  Top 0.2: 120.4,90.3 120.3,90.4
  Top 0.406: 120.3,90.4 120.3,96.7
N$482
  Bottom 0.406: 113.3,97.7 114.3,97.7 116.1,95.9
N$483
  Bottom 0.2: 122.1,98.4 121.9,98.4 121.1,99.2 114.5,99.2 113.3,98
N$484
  Bottom 0.2: 131.4,97.8 131.5,97.9
  Bottom 0.406: 128.8,97.8 131.4,97.8
N$485
  Bottom 0.406: 136.3,97.7 137.2,97.7 139.1,95.8
N$486
  Bottom 0.406: 140.5,98 142.4,98 143.6,96.8
N$487
  Top 0.406: 145.5,98 142.7,98 140.5,95.8
N$488
  Top 0.406: 143.8,96.4 143.8,93.1 140.9,90.2
N$489
  Bottom 0.61: 122.2,95.6 122.2,93.6 125.5,90.3
N$490
  Top 0.15: 78,8.6 78,8.3
N$491
  Bottom 0.406: 146.1,88.1 146.1,95.1 145.8,95.4
N$492
  Top 0.2: 125.5,90 125.5,87.5 122.8,84.8
N$493
  Top 0.406: 108.2,98.2 106.1,98.2 105.7,97.8
N$494
  Top 0.2: 104.8,87.2 104.8,86.6
N$495
  Top 0.2: 104.7,87 104.7,86.9
  Top 0.813: 104.7,87 107,89.3 107,90.9 103.1,94.8 103.1,96.1 103,96.2
N$496
  Top 0.15: 111.1,86.3 111.1,88 104.3,94.7 104.3,99 99.1,99 98.2,98.1 98.2,93.4 97.6,92.8 92.2,92.8 90.7,94.3 83.6,94.3 82.3,95.6
N$497
  Top 0.15: 84.7,95.8 85.7,94.8 91.1,94.8 92.5,93.4 96.9,93.4 97.5,94 97.5,98.2 98.8,99.5 110.3,99.5 111.3,98.5 111.3,88.8 112.4,87.7 112.4,86.3
N$498
  Top 0.15: 111.1,79.8 111.1,81.7 110.3,82.5 107.9,82.5
N$499
  Top 0.15: 112.4,80.1 112.4,82.2 111.1,83.5 106.7,83.5 106.3,83.9
N$500  (via drill 0.5)
  Bottom 0.15: 87.3,96.2 92.9,96.2 94.7,94.4 100.5,94.4 101.5,93.4 101.5,89 104.3,86.2 107.2,86.2 107.9,85.5 v107.9,82.5
N$501
  Bottom 0.15: 152,83.1 154.9,83.1 155.4,83.6 158,83.6 158.7,82.9 158.7,80.6 157.8,79.7 152.8,79.7 152.7,79.6
N$502  (via drill 0.5)
  Bottom 0.15: 79.5,96 79.5,95 92.6,95 94.3,93.3 100.5,93.3 101,92.8 101,88.6 104,85.6 106.2,85.6 v106.2,84
N$503
  Top 0.15: 117.4,81.6 117.4,84.9 | 117.4,81.6 117.4,80.1 117.5,80 | 117.4,81.6 115.9,81.6 114.9,80.6
N$504
  Top 0.15: 113.7,79.6 114.9,79.6
N$505
  Top 0.15: 118.8,79.6 117.5,79.6 117.4,79.5
N$506
  Top 0.15: 93.6,44.9 93.6,45.2 96.7,48.3
N$507
  Top 0.15: 91.3,43.2 91.5,43.2 92.5,42.2 97.4,42.2 97.4,46.8 100.8,46.8 102,48
N$508  (via drill 0.5)
  Top 0.15: 94.4,49.2 94.4,47.4 93.7,46.7 90.5,46.7 89.3,45.5 89.3,42.7 90.8,41.2 98.1,41.2 98.1,37.1 v97.3,36.3
N$509
  Top 0.15: 99.6,49.9 99.6,50.3 97.9,52.1 92.9,52.1 92.9,47.1 90.2,47.1 88.8,45.7 88.8,42.6 90.8,40.6 97.4,40.6 97.4,38.1 95.4,36.1
N$510  (via drill 0.5)
  Bottom 0.15: v95.4,36.2 95.5,36.2 96.5,37.2 97.8,37.2 98.5,36.5 98.5,34.5 107.3,34.5 109.1,32.7
N$511
  Bottom 0.305: 126.8,52.5 126.8,54.9 129.1,57.2 149.5,57.2 156.2,63.9
N$512
  Top 0.2: 113.6,86.3 113.7,86.4 113.7,87.4 114.2,87.9 120.8,87.9 126.1,93.2
  Top 0.61: 126.1,96.3 126.1,93.2 135.5,93.2 140.1,88.6 141.5,88.6 143,90.1 148.6,90.1 150.9,87.8 152.8,87.8
N$513
  Top 0.2: 74.2,75.4 72.9,75.4 72.1,74.6 72.1,62.4 71.1,61.4 67.7,61.4
N$514
  Bottom 0.15: 78.7,76.6 78.7,78.8
  Bottom 0.2: 81.5,78 80.1,78 78.7,76.6
N$515
  Bottom 0.2: 75.9,75.4 77.5,75.4 78.7,76.6
N$516
  Top 0.15: 112.9,72.9 114.6,72.9
N$517
  Bottom 0.15: 115.3,72.9 119.4,72.9 120.1,72.2 120.1,53.2 123.9,49.4 127.8,49.4 129,50.6
N$518
  Bottom 0.15: 112.3,95.8 111.4,96.7 111.4,98.4 110.7,99.1 102.6,99.1 101.8,98.3 101.8,94.6 102.7,93.7 102.7,89.3 104.6,87.4 107.8,87.4 109.3,85.9 109.3,82 108.2,80.9 107.3,80.9 102.7,85.5 99.8,85.5 96.9,82.6 96.3,82.6 94.9,81.2 94.9,79.6 101.4,79.6 104.3,76.7 104.3,74.6 101.4,71.7 96.6,71.7 95.6,72.7 95.6,74.9 96.2,75.5 96.3,75.5
N$519  (via drill 0.5)
  Bottom 0.15: 134.6,82.5 132.9,84.2 128.6,84.2 123.2,78.8 108.6,78.8 102.4,85 100,85 100,82.8 99.3,82.1 96.5,82.1 v96.5,81
N$520
  Bottom 0.813: 15.6,28.9 18.8,28.9
N$521
  Bottom 0.813: 78.8,84.7 91.9,84.7
N$522
  Bottom 0.61: 105.4,90 116.4,90 122.1,95.7
N$523  (via drill 0.7)
  Top 0.813: 104.5,86.9 104.5,88.1 104.1,88.5 101.9,88.5 100.3,86.9 96.3,86.9 94.1,84.7 v91.9,84.7
N$524
  Top 0.15: 154.7,85.2 154.5,85.2
N$525
  Top 0.15: 132.7,45.3 139,45.3 140,44.3 140,28.8 137.5,26.3 134.3,26.3
N$526
  Bottom 0.15: 115.4,49.6 104.9,49.6 102.5,47.2 92.5,47.2 91.7,48
N$527
  Bottom 0.15: 101.4,59.9 101.5,59.9 | 101.4,59.9 103.8,59.9 | 97.5,59.9 101.4,59.9
N$528
  Top 0.15: 96.9,62.6 96.9,60.7 96.3,60.1
N$529  (via drill 0.5)
  Bottom 0.15: v102.8,58.7 96.6,58.7 96.2,59.1 96.2,60
N$530  (via drill 0.5)
  other vias: 103.8,59.9
N$531
  Top 0.15: 103.8,59.9 116.7,59.9 117.2,59.4 117.2,57
N$533
  Bottom 0.15: 67.1,68.9 50.3,68.9 48.9,70.3 48.9,77.6 49.1,77.8
N$534  (via drill 0.5)
  Top 0.15: 99.2,63 99.2,76.5 94,76.5 v93.1,75.6
  Bottom 0.15: 74.3,83.1 72.5,83.1 72.5,73.8 91.3,73.8 v93.1,75.6
N$535
  Top 0.15: 98.4,63.1 98.4,74.2 95.2,74.2 93.9,72.9
N$536  (via drill 0.5)
  Bottom 0.15: 73.7,80.2 73.1,79.6 73.1,74.3 90.1,74.3 92.5,76.7 94.2,76.7 94.6,76.3 94.6,73.6 v93.9,72.9 94.3,72.9 96.1,71.1 111.4,71.1 114.3,74 119.1,74 120.7,72.4 120.7,62.9 121.2,62.4 131.6,62.4 134.3,65.1 145.6,65.1 147.6,63.1 153.8,63.1 156.1,65.4 158.4,65.4 159.2,64.6 159.2,63.1 158.8,62.7 156,62.7 149.3,56 149.3,49.2 149.8,48.7 153.8,48.7
N$537
  Bottom 0.15: 51.5,77.6 51.5,69.9 51.8,69.6 65.4,69.6 65.9,70.1 68.8,70.1 69.4,69.5 69.4,67 68.9,66.5 68.3,66.5
N$538
  Top 0.15: 61.1,49.1 67.1,49.1 67.1,57 67.9,57.8 76.9,57.8 79,59.9 89.5,59.9 92.1,62.5
N$539  (via drill 0.5)  (1 unrouted)
  Top 0.15: 61.2,54.8 63,54.8 63.6,55.4
  other vias: 63.7,55.6
N$540
  Bottom 0.15: 138.6,36.9 131.5,44 128.5,44 115.9,56.6
N$541
  Bottom 0.15: 87.8,55.6 88.2,56 115.4,56 128.1,43.3 131.1,43.3 137.1,37.3 137.1,34.5 138.1,33.5 139.6,33.5 140,33.9 140,39.8 139,40.8
N$542
  Top 0.15: 90.2,68.5 87.1,68.5 86.9,68.7 84.6,68.7
N$543
  Top 0.15: 61.4,53.2 64.7,53.2 64.7,54.1 | 90,67.8 81.7,67.8 76.7,62.8 76.7,60.7 76,60 66.7,60 64.7,58 64.7,54.1 | 64.7,54.1 64.7,54
N$544
  Top 0.15: 61.3,52.4 65.3,52.4 65.3,53.3 | 65.3,53.3 65.3,53.2 | 65.3,53.3 65.3,57.8 67,59.5 76.2,59.5 77.3,60.6 77.3,62.3 81.9,66.9 90.1,66.9
N$545
  Top 0.15: 90.3,69.3 85.8,69.3 85.5,69.6 83.1,69.6 82.8,69.3 82.8,68.8
N$546
  Top 0.2: 94,32.8 94,34.5 98.1,34.5 99.5,35.9 99.5,41.8 100.8,43.1
N$547
  Top 0.15: 61.2,50.9 66.5,50.9 66.5,51.7 | 66.5,51.7 66.5,51.6 | 66.5,51.7 66.5,57.2 67.6,58.3 76.6,58.3 78.5,60.2 78.5,60.8 82.7,65
N$548
  Top 0.15: 52.1,41.8 52.1,31 51.5,30.4
N$549
  Top 0.15: 51.3,41.8 51.3,31.5 50.2,30.4
N$550  (via drill 0.5)
  other vias: 51.5,30.3
N$551  (via drill 0.5)
  other vias: 50.1,30.3
N$552
  Bottom 0.15: 62,15 58.1,15 56.6,16.5 56.6,25 55.4,26.2 54.1,26.2 50.3,30
N$553
  Bottom 0.15: 64.5,20.7 64.5,20 64.1,19.6 58.7,19.6 57.2,21.1 57.2,25.3 55.7,26.8 54.8,26.8 51.6,30
N$554
  Top 0.15: 96.8,53.9 100.2,53.9 104.6,49.5 104.6,46.5 103.8,45.7
N$555  (via drill 0.5)
  Top 0.15: 61.3,51.6 65.9,51.6 65.9,52.5 | 65.9,52.5 65.9,52.4 | 65.9,52.5 65.9,57.5 67.3,58.9 76.4,58.9 77.9,60.4 77.9,61.7 82.2,66 84,66 v84.6,65.4
  Bottom 0.15: 96.2,43.1 96.2,41.8 86.6,41.8 81.4,47 81.4,62.2 v84.6,65.4 84.6,68.5
N$556
  Top 0.15: 38.2,33.7 38.2,35.4 38.5,35.7
N$557
  Bottom 0.15: 66.7,93.5 61.2,88 53.1,88 52.7,87.6 52.7,84.6 51.7,83.6 50,83.6 | 50,83.6 49.9,83.6 | 50,83.6 48.4,83.6 40.2,75.4 40.2,56.9 43.1,54 43.1,45.2 42.4,44.5 42.4,43.9
N$558
  Top 0.15: 60.8,61.5 60.8,57.2 59.8,56.2 59.8,54.7 56.2,54.7 56.2,50.3 49.7,43.8 49.7,38.1
  Top 0.2: 56.1,57.5 56.1,60.9 56.7,61.5 60.8,61.5 66.4,61.5
N$559
  Top 0.2: 58.5,42.1 58.5,43.2 50.5,43.2 50.5,41.8
N$560
  Top 0.15: 41.9,45.2 45.7,45.2
N$561
  Top 0.15: 48.1,42.2 48.1,43.4 48.4,43.7 48.4,45.2 48,45.6
N$562
  Top 0.15: 45.5,44.4 43,44.4 42.5,43.9
N$563
  Bottom 0.15: 71.8,96.5 71.8,97.6 67.8,97.6 67.8,92.9 62.5,87.4 58.1,87.4 58.1,85.1 56,83 48.5,83 40.7,75.2 40.7,57.1 43.6,54.3 43.6,43
N$564
  Top 0.15: 47.3,41.9 47.3,43.7 47.6,44
N$565  (via drill 0.5)
  Bottom 0.15: v47.4,44.1 45,44.1 44.2,44.9 44.2,54.5 41.3,57.5 41.3,74.9 48.8,82.4 56.5,82.4 58.8,84.7 58.8,86.8 63,86.8 68.4,92.2 70.6,92.2 71.7,93.3
N$566  (via drill 0.5)
  Bottom 0.15: 64.3,93.2 59.6,88.5 50.9,88.5 50.2,87.8 50.2,84.7 49.8,84.3 48.3,84.3 39.8,75.8 39.8,75.2 39.7,56.6 41.9,54.4 v41.9,45.3
N$567  (via drill 0.5)
  Bottom 0.15: v47.9,45.6 45.2,45.6 44.8,46 44.8,54.8 41.8,57.8 41.8,74.6 49.1,81.9 56.9,81.9 59.5,84.5 59.5,86.2 63.4,86.2 68.7,91.5 71.7,91.5 73.3,93.1 73.3,94.2 72.8,94.7 70.4,94.7 69.4,95.7
N$568
  Bottom 0.15: 69,93.9 69,94.1 68.2,94.9 68.2,97.2 70.2,97.2 70.6,96.8 70.6,95.5 71,95.1 73,95.1 73.8,94.3 73.8,92.8 72,91 69,91 63.7,85.7 60.1,85.7 60.1,84.3 57.2,81.4 49.4,81.4 42.4,74.4 42.4,58 45.4,55 45.4,47.8 46,47.2 47.7,47.2
N$569  (via drill 0.5)
  other vias: 47.9,47.1
N$570
  Top 0.15: 48.9,42.1 48.9,46.1 48.1,46.9
N$571
  Top 0.15: 78.6,26.3 78.5,26.3 78.5,20.5 77.3,19.3 77.3,15
N$572
  Top 0.15: 62.1,22.8 62.1,23.3 62.7,23.9 75.1,23.9 76,23 76,13 76.4,12.6 78.2,12.6 78.7,13.1 78.7,19.7 79.1,20.1 79.1,24.7 79.7,25.3 85.5,25.3 85.9,25.7 85.9,34.1 | 85.9,34.1 84.5,34.1 | 85.9,34.1 91.1,34.1 91.5,33.7 91.5,32.5
N$573
  Bottom 0.305: 74,31.8 86.3,31.8 88.5,34 90.5,34 91.4,33.1
N$574
  Bottom 0.15: 104.5,31.1 104.9,31.1 106.4,29.6 109.6,29.6 110.4,30.4 110.4,33 108.3,35.1 102,35.1 99.5,37.6 96,37.6 95.6,37.2 88.2,37.2 87.9,36.9 73.9,36.9
N$575
  Top 0.15: 61.2,47.6 62.6,47.6 63.3,46.9 63.3,43.4 63.7,43
N$577
  Top 0.15: 82.1,32.6 82.1,32.7
  Top 0.2: 78.6,31.5 79.6,31.5 79.6,28.9 | 94,32.7 91.5,35.2 82.4,35.2 82.1,34.9 82.1,32.6 82.1,30.2 | 82.1,32.7 83.3,32.7 | 82.1,30.2 83.1,30.2 | 83.4,27.7 82.1,27.7 82.1,28.2 | 82.1,28.2 82.1,30.2 | 79.6,28.2 82.1,28.2 | 78.5,26.4 79.6,26.4 79.6,28.2 | 79.6,28.2 79.6,28.9 | 79.6,28.9 78.5,28.9
N$578
  Bottom 0.15: 80.8,29.1 80.8,25.7 82.1,24.4 88.8,24.4
N$579
  Top 0.15: 95.1,53.5 95.1,52.6 99.5,52.6 100.8,51.3 100.8,47.9 100.2,47.3 98.6,47.3 98.2,47.7 98.2,50.9 97.6,51.5 96.3,51.5 95.7,50.9 95.7,48 94,46.3 90.7,46.3 89.7,45.3 89.7,43.1 91.1,41.7 98.7,41.7 | 98.7,41.7 98.7,43.2 | 98.7,41.7 98.7,36.1 97.8,35.2 93.7,35.2 92.5,36.4 91.4,36.4
N$580
  Top 0.15: 60.9,46 59.7,46 58.9,45.2 58.9,44.7
N$581
  Bottom 0.15: 74.1,39.4 75.2,39.4 75.6,39 75.6,37.7 75.9,37.4 87.4,37.4 87.8,37.8 95.2,37.8 95.6,38.2 100.4,38.2 102.6,36
N$582
  Bottom 0.15: 102.6,36 108.1,36 111.1,33 111.1,30 110.1,29 106,29 105.1,29.9 102.5,29.9 101.5,30.9
N$583  (via drill 0.5)
  Top 0.15: 76.9,34 77.1,34
  Top 0.2: v68,54.5 68,41.9 71.6,41.9 72.1,41.4 74.6,41.4 76.9,39.1 76.9,34 76,34 75.7,33.7 75.7,31 75.3,30.6 71.6,30.6 70.8,29.8 70.8,28.1 71.7,27.2
N$584  (via drill 0.5)
  Top 0.15: 60.9,46.8 58.8,46.8 57.3,45.3 v57.3,44.6
  Bottom 0.15: v57.3,44.6 57.3,45.3 58.2,46.2 59.5,46.2 60.2,45.5 60.2,44.1 59.5,43.4 59.5,26.5 60.8,25.2 72.2,25.2 74.5,22.9
N$585  (via drill 0.5)
  Bottom 0.15: v58.9,44.6 58.9,26.1 60.5,24.5 70.9,24.5 70.9,16.2 72,15.1
N$586
  Top 0.813: 46.7,93.1 50.6,93.1 53.3,95.8
N$587
  Bottom 0.2: 32,99.3 31.9,99.3 | 30,99.3 29.8,99.3 29.4,98.9
  Bottom 0.61: 31.9,99.3 31.9,98.1 | 29.4,98.9 29.4,98
  Bottom 0.813: 53.2,98.3 52.2,99.3 32,99.3 30,99.3 23.4,99.3 | 23.4,99.3 15.8,99.3 14.9,98.4 | 23.4,99.3 23.4,97.9
N$588
  Bottom 0.2: 47.2,98 50.8,98
N$589
  Bottom 0.2: 47.2,97.9 50.8,97.9
N$590
  Bottom 0.3: 39.6,96.1 39.6,95.3 39.1,94.8 27.1,94.8 26.2,94
N$591
  Top 0.15: 45.9,54 46.7,54 48.3,52.4 52.9,52.4 52.9,53 53.4,53.3
N$593
  Top 0.15: 46,52.4 47.3,52.4 48.2,51.5 54.9,51.5
N$594
  Bottom 0.15: 122.2,12.3 120.4,14.1 120.4,26.1 107.1,39.4 77.9,39.4 75.6,41.7 68.5,41.7 61.5,48.7 59.8,48.7 | 59.8,48.7 59.9,48.7 | 53.5,53.2 53.5,50.6 53,50.1 51.2,50.1 50.1,48.9 50.1,47.1 50.7,46.5 56.6,46.5 57.6,47.5 57.6,48.4 57.9,48.7 59.8,48.7
N$595
  Bottom 0.15: 150,14.5 148.8,13.3 146.9,13.3 146.3,13.9 134.7,13.9 134,14.6 132.3,14.6 131.2,15.7 131.2,21.4 130.7,21.9 128.7,21.9 127.1,23.5 127.1,28 126,29.1 121.3,29.1 110.2,40.2 78.3,40.2 76,42.5 69,42.5 64.9,46.6 64.9,49.7 63.7,50.9 61.9,50.9 61.9,49.8 61.3,49.2 57.6,49.2 57,48.6 57,47.9 56.5,47.4 51.3,47.4
N$596
  Bottom 0.15: 114.7,25.1 113.7,26.1 113.7,32 106.7,39 77.6,39 75.3,41.3 65.3,41.3 65,41.6 65,43.7
N$597
  Bottom 0.15: 122.3,22.4 121.1,23.6 121.1,26.1 107.4,39.8 78.1,39.8 75.8,42.1 68.8,42.1 63.2,47.7 63.2,49.9
N$598  (via drill 0.5)
  Top 0.15: 61,51.6 58.8,51.6 v58.8,47.8
  Bottom 0.15: v58.8,47.8 61.1,45.5 61.1,35.8 62.4,34.5 72.5,34.5
N$599
  Top 0.15: 61.3,48.4 62.9,48.4 64.1,47.2 64.1,44.4 64.6,43.9
N$600
  Top 0.15: 63.1,50 61.2,50
N$602
  Bottom 0.15: 114.7,14.9 113,16.6 113,31.8 106.2,38.6 77.3,38.6 75,40.9 64.7,40.9 63.8,41.8 63.8,42.8
N$603
  Bottom 0.15: 150,17 149.9,17 148.8,15.9 139.6,15.9 138.3,14.6 134.8,14.6 134.1,15.3 134.1,19.8 131.4,22.5 129,22.5 127.7,23.8 127.7,28.3 126.3,29.7 121.5,29.7 110.6,40.6 78.5,40.6 76.2,42.9 69.2,42.9 65.4,46.7 65.4,49.8 63.9,51.3 61.3,51.3 61.3,49.9 61,49.6 52.6,49.6 52.2,49.2
N$604
  Top 0.15: 90.3,74.9 89.3,74.9 88.5,74.1 88.5,71.2 87.6,70.3
N$605  (via drill 0.5)
  Bottom 0.15: v55.1,51.5 60.9,51.5 61.1,51.7 64.1,51.7 65.9,49.9 65.9,46.8 69.4,43.3 76.4,43.3 78.7,41 111.1,41 121.7,30.4 141.9,30.4 147.3,25 148.9,25 150,26.1
N$606  (via drill 0.5)
  Top 0.15: 129.6,16.5 129.6,14.8 130.8,13.6 v133,13.6
N$607  (via drill 0.5)
  Bottom 0.15: 150,28.7 150,28.6 149,27.6 145.6,27.6 142.2,31 122,31 111.6,41.4 78.9,41.4 76.6,43.7 69.7,43.7 66.4,47 66.4,50 64.1,52.3 60.9,52.3 60.5,51.9 57.3,51.9 55.9,53.3 v55.1,53.3
N$608
  Top 0.15: 92.8,62.6 92.8,61.5 92.4,61.1 91.4,61.1 89.7,59.4 79.2,59.4 76.9,57.1 72.1,57.1 70,55
N$609  (via drill 0.9)
  Bottom 0.813: 16.8,65.1 17.5,64.4 17.5,62.3 16.3,61.1 11.8,61.1 10.9,60.2 10.9,56.5 9.2,54.8 9.2,43.7 9.6,43.3 9.6,42 10.1,41.5 10.1,38 9.1,37 9.1,29.1 12.1,26.1 12.1,21.8 13.2,20.7 18.1,20.7 24.8,14 v26.9,14
N$610  (via drill 0.5)
  Bottom 0.15: v69.9,54.6 69.9,53.6 69.3,53 67.1,53 66.7,53.4 60,53.4 58.3,55.1 50.9,55.1 50.9,53 48.5,50.6 48.5,48 48.9,47.6 48.9,41.8 41.6,34.5 40.7,34.5
N$611
  Top 0.15: 93.7,62.8 93.7,61.5 92.8,60.6 91.6,60.6 89.9,58.9 79.5,58.9 77.2,56.6 72.3,56.6 71.2,55.5 71.2,54.4
N$612
  Bottom 0.15: 71.2,54.2 71.2,53.4 70.3,52.5 65.1,52.5 64.7,52.9 57.7,52.9 56.2,54.4 51.5,54.4 51.5,51.6 49.4,49.5 49.3,41 49.3,40.8 41.6,33.1 40.8,33.1 40.7,33
N$613
  Bottom 0.406: 18,10.7 18,8.9 17,7.9 14.6,7.9 | 17.4,16.5 15.9,16.5 14.2,18.2 12.2,18.2 11.4,17.4 11.4,11.2 14.6,8 14.6,7.9 | 14.6,7.9 14.6,5.4 14.7,5.3
N$614
  Top 0.15: 90.6,65.3 91.7,65.3 92,65.6 92,73.2 94.8,76 96,76 96.4,75.6
N$615  (via drill 0.5)
  other vias: 87.8,70.5
N$616
  Top 0.15: 112.4,49.4 112.4,48.9 116,45.3 118,45.3 120,43.3
N$617  (via drill 0.5)
  Bottom 0.15: v136.1,44.2 147.8,44.2 150,46.4 153.6,46.4
N$618
  Bottom 0.15: 78.6,55.5 78.1,56 65.3,56 64.9,55.6 63.7,55.6
N$619
  Top 0.15: 100.8,63 100.8,74.3 101.7,75.2
N$620  (via drill 0.5)
  Top 0.15: 60.9,54 57.5,54 57,53.5 57,49.6 v52.1,44.7
  Bottom 0.15: v52.1,44.7 50.6,44.7 49.9,44 49.9,39.7 42.3,32.1 26.6,32.1 26.6,46.4 27.4,47.2 27.4,49.7 21.7,55.4 21.7,69.2 17.9,73 17.9,73.8 19.4,75.5 19.4,77.1 18.3,78.2 11.5,78.2 11,77.7
N$621
  Bottom 0.15: 4.5,69.2 4.5,73.4 4.1,73.8 0.9,73.8 0.9,83.2 1.7,84 4.2,84 7.4,87.2 12.1,87.2 13.2,86.1 13.2,81.7 14.9,80 18.8,80 20.4,81.6 42.2,81.6 47,86.4 47,87.5 47.4,87.9 47.4,89.5 48.9,91 55.9,91 56.9,92 56.9,97.6 58.9,99.6 75.7,99.6 76.9,98.4 76.9,94.5 82.5,94.5 83.4,93.6 83.4,90.3 83.6,90.1 91.8,90.1 93.6,88.3 99.9,88.3 99.9,86.7 96.7,83.5 93.4,83.5 92.4,82.5 92.4,79 93.7,77.7 100.3,77.7 101.8,76.2 101.8,75.2
N$622
  Bottom 0.15: 63.7,57.1 78.9,57.1
N$623
  Bottom 0.15: 115.9,56.6 115.4,57.1 87.7,57.1
N$624
  Bottom 0.15: 96.9,50.5 96.9,53.4 96.2,54.1 86.7,54.1 86.2,54.6 86.2,69.1 85.2,70.1 85.2,71 85.7,71.5 87,71.5 87.7,70.8
N$625
  Bottom 0.406: 17.7,69.8 17.6,69.9 | 17.7,69.8 14.6,72.9 | 17.7,69.8 19.1,68.4 19.1,45.2 19.4,44.9 21.3,44.9 21.9,44.3 21.9,41.7 20.8,40.6
N$626
  Bottom 0.15: 135.5,95.9 134.4,97 134.4,98.5 133.2,99.7 112.6,99.7 112.5,99.6 102.4,99.6 101.3,98.5 101.3,94.3 102.1,93.5 102.1,89.1 104.2,87 107.3,87 108.8,85.5 108.8,82.2 108,81.4 107.5,81.4 102.3,86.6 100.4,86.6 96.8,83 96.2,83 94.3,81.1 94.3,79.1 101,79.1 103.7,76.4 103.7,74.8 101.2,72.3 96.9,72.3 96.5,72.7 96.5,73.7 98.1,75.3
N$627  (via drill 0.5)
  Bottom 0.15: 131.6,80.4 129.4,78.2 108.4,78.2 102,84.6 100.5,84.6 100.5,82.6 99.1,81.2 v98.2,81.2
N$628
  Top 0.15: 90.5,64.5 91.9,64.5 92.8,65.4 92.8,73.1 94.3,74.6 98.1,74.6 98.1,75 98.2,75.1
N$629  (via drill 0.7)
  Top 0.61: 114.8,12.2 104.2,12.2 v103.6,11.6
  Bottom 0.15: 91.4,31.3 91.4,31.4
  Bottom 0.61: 91.4,31.3 94.9,27.8 102.5,27.8 102.9,27.4 102.9,12.3 v103.6,11.6
N$631
  Bottom 0.61: 28.9,88.5 28.8,88.4
  Bottom 1.016: 46.3,91.1 46.3,89 45.8,88.5 28.9,88.5
N$632
  Bottom 0.61: 21.2,54.4 21,54.6
  Bottom 0.813: 17.6,76.4 17.6,74.9 16.5,73.8 16.5,72.8 20.6,68.8 20.6,55 21.2,54.4 24,51.6 24,30.2 35.6,30.2 41.7,24.1 41.7,12
N$633
  Top 0.15: 135.5,69.7 134,69.7 133.1,70.6 133.1,72.1 132.4,72.8 128.6,72.8 128.2,73.2 128.2,75 127.2,76 117.6,76
N$634  (via drill 0.6)
  Bottom 0.406: 17.3,88.7 17.3,87.4 16.6,86.7 15.3,86.7 14.5,85.9 14.5,82.6 v15.9,81.2
N$635  (via drill 0.7)  (1 unrouted)
  Top 1.016: v13.5,45.3 11.1,45.3 7.3,49.1 5.7,49.1
  Bottom 1.016: 14.4,43.4 14.4,44.5 13.7,45.2
N$636  (via drill 0.5)
  Top 0.15: v100.3,75.7 100,75.4 100,63
  Bottom 0.15: 3.7,82.7 5,82.7 8.9,86.6 11.9,86.6 12.7,85.8 12.7,81.4 14.6,79.5 19.3,79.5 20.7,80.9 42.5,80.9 47.7,86.1 47.7,87.3 48,87.6 48,89 49.4,90.4 56.6,90.4 57.8,91.6 57.8,97.8 59.1,99.1 75.1,99.1 76.2,98 76.2,94 80.7,94 80.9,93.8 80.9,90.5 81.7,89.7 91.5,89.7 93.3,87.9 99.5,87.9 99.5,87 96.4,83.9 92.8,83.9 91.9,83 91.9,78.8 93.5,77.2 99.6,77.2 100.3,76.5 v100.3,75.7
N$637
  Top 0.2: 50.5,41.6 50.5,37.1 49.5,36.1 43.6,36.1 42.6,35.1
N$638
  Top 0.15: 142.9,55.6 142.9,53.5 139.9,50.5 134.1,50.5 133.1,49.5 133.1,48.4 133,48.3
N$639
  Top 0.15: 135.1,48.1 135.1,49.4 135.6,49.9 141.3,49.9 144.9,53.5 144.9,55.7
N$640
  Top 0.15: 133.1,47.9 133.1,46.7 133.6,46.2 140.9,46.2 143.9,43.2
N$641
  Bottom 0.406: 144.9,55.6 144.9,50.2 147.6,47.5 155.1,47.5 156.3,48.7
N$643
  Top 0.2: 79.5,91.3 79.3,91.3 78.1,90.1 72.1,90.1 | 68.8,85 68.8,89.3 69.6,90.1 72.1,90.1 | 72.1,90.1 72.1,88.2
N$644
  Bottom 0.813: 42.3,11.9 42.4,11.9 | 42.3,11.9 41.5,11.9 | 42.3,11.9 44.9,11.9 45.4,11.4 45.4,9.2
N$645
  Top 0.15: 67,95.8 67.1,95.8 68,94.9 77.7,94.9 78.6,94 80.7,94 80.9,93.8 80.9,90.6 79.9,89.6 75.5,89.6 74.5,88.6
N$646
  Bottom 0.15: 77.2,86.2 77.2,79.7 75.7,78.2
N$647
  Bottom 0.813: 45.4,9 45.4,8.7 44.5,7.8 42.7,7.8 42.7,5.8 41.2,4.3 41.2,2.9
N$648
  Bottom 0.813: 46.6,10.4 46.6,8 45.2,6.6 43.9,6.6 43.9,3
N$649
  Top 0.813: 44.1,17.1 44.9,17.1 45.4,16.6 45.4,14.9 51.2,14.9 51.2,7.9
N$650  (via drill 0.7)
  Top 0.406: v21.7,49.3 17,49.3 15.7,48 12.4,48 11.3,49.1 11.3,51.4 9.3,53.4 3.7,53.4 1.4,55.7 1.4,56.7 2.6,57.9 5.9,57.9 6.2,57.6 12.4,57.6 12.9,57.1
N$651  (via drill 0.6)
  Top 0.406: 144.9,55.8 144.9,58 143.7,59.2 v140.7,59.2
  Bottom 0.406: 137.2,63.4 138.9,63.4 139.5,62.8 139.5,60.4 v140.7,59.2
N$652
  Top 0.406: 14.4,59.7 16.4,59.7 16.8,59.3 16.8,54.9
S$1
  Bottom 0.15: 137.7,74.2 140.2,74.2 144.9,78.9
S$2
  Top 0.305: 154.1,43.9 154.1,43.7
S$3
  Top 0.61: 155.1,54.2 152.1,51.2 152.1,45.4 153.8,43.7
S$4  (via drill 0.9)
  other vias: 25.7,47.9
S$5
  Bottom 0.406: 120,43.3 119.9,43.3 119.9,47.6
S$6
  Top 0.8: 36.3,53.4 30.8,47.9 25.7,47.9
S$7  (via drill 0.5)
  other vias: 29.6,36
S$8  (via drill 0.5)
  other vias: 42.5,43.9
S$9  (via drill 0.5)  (1 unrouted)
  Top 0.15: 49.7,57.4 49.7,59.2 v50.5,60 | 90.3,66.1 88.5,66.1 v88,65.6
  Bottom 0.15: 50.4,60 55.1,60 61.2,53.9 67.2,53.9 67.6,53.5 68.6,53.5 69,53.9 69,55.2 69.3,55.5 77.3,55.5 78.3,54.5 80.3,54.5 80.8,55 80.8,68.3 82.5,70 83.4,70 85.6,72.2 87.7,72.2 89,70.9 89,66.6 v88,65.6
S$10  (via drill 0.5)
  Top 0.15: 45.6,43.6 44.1,43.6 v43.5,43
S$11  (via drill 0.5)
  other vias: 40.9,47.7
S$12  (via drill 0.5)
  Top 0.15: 87.7,57.1 v87.6,57.1 v79,57.1
S$13  (via drill 0.5)  (1 unrouted)
  Top 0.15: 42.7,37.2 48.8,37.2 49.7,38.1
  Bottom 0.15: v42.6,37.3 41.1,35.8 v38.6,35.8
S$14
  Top 0.15: 45.2,51.6 41.5,51.6 40.9,51 40.9,49.2
S$15
  Top 0.15: 54.9,53.2 53.7,52 48.2,52 47,53.2 46,53.2
S$16  (1 unrouted)
S$17  (via drill 0.5)
  other vias: 53.4,53.3
S$18  (via drill 0.5)
  other vias: 49.9,53.3
S$19  (via drill 0.5)
  Top 0.15: 45.9,49.2 v52,49.2
S$20
  Bottom 0.15: 67.4,33.2 67.5,33.3
  Bottom 0.2: 72.8,29.4 69.2,29.4 67.4,31.2 67.4,33.2
S$21
  Bottom 0.813: 147.7,23.8 145.5,23.8 142.8,26.5 137.4,26.5 136.1,27.8 129.9,27.8 129.3,27.2 129.3,25.9
S$22  (via drill 0.5)
  other vias: 63.8,42.9
S$23  (via drill 0.5)
  Top 0.15: v51.3,47.5 50.4,48.4 45.9,48.4
S$24  (via drill 0.5)
  other vias: 46.1,58.8
S$25  (via drill 0.5)
  other vias: 44.4,59.6
S$26  (via drill 0.5)
  Bottom 0.15: 46.2,58.7 46.9,58 46.9,56.4 47.3,56 v47.3,54.7
S$27
  Bottom 0.813: 12.4,96.1 14.5,94 20.8,94 | 20.8,94 20.8,96.1 | 20.8,94 26.3,94 17.8,85.5 17.8,84.2
S$28
  Bottom 0.406: 15.9,75.4 14.6,74.1 14.6,73
S$29  (via drill 0.6)
  other vias: 16,75.4
S$30  (via drill 0.9)
  other vias: 16.7,65.2
S$31  (via drill 0.5)
  other vias: 4.5,68.8
S$32  (via drill 0.9)
  Top 0.813: v17.8,76.8 v17.8,83.7
S$33
  Top 0.406: 16,75.3 16,81.2
S$34  (via drill 0.5)
  Bottom 0.15: v6.7,58.6 6.1,58.6 4.9,59.8 4.9,67.5 3.4,67.5
S$35  (via drill 0.5)
  Bottom 0.15: v113,77.1 112.9,77.2
S$36  (via drill 0.6)
  other vias: 114.9,72.9
S$37  (via drill 0.5)
  other vias: 101.8,75.3
S$38  (via drill 0.5)
  other vias: 98.3,75.4
S$39  (via drill 0.5)
  Top 0.15: v97.5,73.2 96.1,71.7 96.1,62.8
S$40  (via drill 0.5)
  other vias: 96.3,75.6
S$41
  Top 0.15: 98.2,81.1 96.4,79.3 95.3,79.3 95.3,78.6
S$42
  Top 0.15: 96.3,80.9 96.2,81 95.5,81 94.5,80 94.5,78.5
S$43
  Top 0.15: 90.9,80.4 92,80.4 92.9,79.5 92.9,79.4 | 93.5,82.1 92.9,81.5 92.9,79.4 | 92.9,78.2 92.9,79.4
S$44
  Top 0.15: 93.6,78.6 93.6,80.6 94.7,81.7 94.7,83.2 94.3,83.6 91.5,83.6 90.8,84.3 90.8,85.8 91.2,86.2
S$45  (via drill 0.5)
  other vias: 101.6,83.8
S$46
  Top 0.15: 92,78.6 92,79.1 91.8,79.3 87.6,79.3 | 87.7,80.4 87.7,79.4 87.6,79.3 | 86.5,78.2 87.6,79.3
S$47  (via drill 0.5)
  Top 0.15: v78.7,55.5 v87.7,55.5
S$48  (via drill 0.5)
  Top 0.15: 97.7,62.6 97.7,60.2 v97.5,60 97.4,59.9
S$49  (via drill 0.5)
  other vias: 96.2,60.1
S$50
  Top 0.15: 102.8,57 102.8,58.8
S$51  (via drill 0.5)
  Top 0.15: 94.5,62.6 94.5,61.5 93,60 91.9,60 91.1,59.2 91.1,56 92.3,54.8 92.3,48.7 v91.7,48.1
S$52  (via drill 0.5)
  other vias: 84.6,68.7
S$53  (via drill 0.5)
  Bottom 0.15: v82.8,65 v82.8,68.7
S$54  (via drill 0.5)
  other vias: 63.2,50
S$55
  Top 0.3: 152.3,77.1 134.2,77.1 131.4,74.3
S$56  (via drill 0.5)
  Top 0.15: 61.2,55.5 62.1,55.5 v63.7,57.1
S$57  (via drill 0.5)
  other vias: 71.2,54.3
S$58  (via drill 0.5)
  other vias: 64.9,43.7
S$59  (via drill 0.5)
  Top 0.15: 67.1,33.6 v67.4,33.3
  Top 0.2: 66,33.6 67.1,33.6
S$60
  Top 0.15: 40.7,33 40.7,32 39.4,30.7 39.4,28.2
S$61  (via drill 0.5)
  Top 0.15: v40.6,34.5 39.4,34.5
S$62  (via drill 0.6)
  other vias: 27.9,19
S$63
  Bottom 0.15: 106.6,32.9 105.5,34 97.9,34 97.3,34.6 97.3,36.2
S$64  (via drill 0.5)
  other vias: 91.4,36.4
S$65  (via drill 0.5)
  Top 0.15: 78.3,32.8 80.4,32.8 80.8,32.4 v80.8,29.3
S$66  (via drill 0.8)
  Top 0.15: 95.8,13.1 95.9,13.2
  Top 0.813: v95.8,10.7 95.8,13.1
S$67
  Top 0.15: 84.4,90.9 83.7,90.9 82.8,90 81.1,90 78.8,87.7 78.8,85.8 75.9,82.9
S$68
  Bottom 0.15: 96.1,85.1 95.3,85.9 94.2,85.9 91.4,88.7 88.4,88.7 88.1,88.4
S$69
  Bottom 0.15: 82.8,86.3 82.8,85
S$70
  Bottom 0.15: 85.6,86.1 86.2,85.5 90,85.5 90.7,86.2 91.3,86.2
S$71  (via drill 0.5)
  other vias: 40.7,33.1
S$72  (via drill 0.9)
  Bottom 0.61: v15.3,33.8 15.3,37.1
S$73
  Top 0.15: 97.6,83.7 97.5,83.7 96.3,84.9
S$74  (via drill 0.5)
  other vias: 91.1,86.3
S$75
  Bottom 0.2: 74.1,26.8 75.9,26.8 79.8,30.7 88.3,30.7 88.6,31
S$76  (via drill 0.5)
  other vias: 93.7,82.3
S$77  (via drill 0.5)
  other vias: 96.2,85
S$85
  Top 0.15: 106.8,30.8 106.7,30.9

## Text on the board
Top: TOP-Layer
Bottom: BOT-Layer
tPlace: GND | ON | OFF | +5V | +4V | - | + | KOLIS 2 | August 2007 | Florian Scherb | RX | TX | RX | TX | Rot = TOP-Layer | Florian Scherb | Blau = BOT-Layer | Tel.: 07306 6564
